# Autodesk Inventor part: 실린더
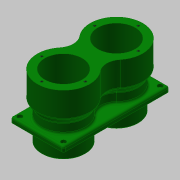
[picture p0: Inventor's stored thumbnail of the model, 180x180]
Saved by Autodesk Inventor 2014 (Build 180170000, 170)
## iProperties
Created: 2016-11
Part Number: 실린더
Material: 알루미늄 6061
Document SubType Name: Modeling
Designer: mduedu
Density: 2.71 g/cm^3
Mass: 1199.26 g
Surface Area: 1038.68 cm^2
Volume: 442.531 cm^3
Appearance: 진녹색
Author: mduedu
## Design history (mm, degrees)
sketch "스케치1"
  geometry: L1 (0, 0)-(0, 101); L2 (30, 0)-(30, 101); L3 (30, 101)-(42, 101); L4 (42, 101)-(42, 61); L5 (42, 61)-(35, 51); L6 (35, 51)-(35, 0); L7 (35, 0)-(30, 0)
  constraints: 14 end point, 4 parallel, 2 horizontal alignment, 1 perpendicular, 1 vertical
  dimensions: "d0" = 101 distance of L1.start L1.end; "d1" = 60 diameter of L2.end L1; "d2" = 84 diameter of L3.end L1; "d3" = 70 diameter of L6.end L1; "d4" = 40 distance of L3.end L4.end; "d5" = 50 vertical distance of L5.end L3.end
revolve "회전1" stored, may be unused: angle "d6" = 90 deg
node "작업 평면1"
sketch "스케치2"
  geometry: L1 (-42.5, -42.5)-(42.5, -42.5); L2 (42.5, -42.5)-(42.5, 42.5); L3 (42.5, 42.5)-(-42.5, 42.5); L4 (-42.5, 42.5)-(-42.5, -42.5); L5 (-42.5, -42.5)-(42.5, 42.5); L6 (42.5, -42.5)-(-42.5, 42.5); C1 r 35 at (0, 0) reference; C2 r 35 at (0, 0); 1 further point
  constraints: 12 end point, 2 midpoint, 2 parallel, 2 perpendicular, 1 centre point, 1 coincident, 1 concentric, 1 horizontal
  dimensions: "d8" = 85 distance of L2.end L3.end
extrude "돌출1" join sketch "스케치2" distance "d10" = 8; taper "d11" = 0 deg
chamfer "모따기1" distance "d14" = 1; stored, may be unused: second distance "d15" = 2, angle "d16" = 45 deg
chamfer "모따기2" distance "d17" = 5; stored, may be unused: second distance "d18" = 2, angle "d19" = 15 deg
sketch "스케치3"
  geometry: L1 (-35, -35)-(35, -35); L2 (35, -35)-(35, 35); L3 (35, 35)-(-35, 35); L4 (-35, 35)-(-35, -35); L5 (-35, -35)-(35, 35); L6 (35, -35)-(-35, 35); 3 further points
  constraints: 12 end point, 2 coincident, 2 midpoint, 2 parallel, 1 horizontal, 1 perpendicular
  dimensions: "d20" = 70 distance of L3.end L2.end; "d21" = 70 distance of L2.end L1.end
sketch "스케치4"
  geometry: 2 further points
  constraints: 2 other
hole "구멍1" sketch "스케치4" at (-35, 35), (35, 35) diameter "d22" = 4.5; stored, may be unused: countersink angle "d26" = 90 deg, drill point angle "d28" = 0 deg; dims "d23" = 6, "d24" = 8, "d25" = 4.6, "d27" = 8
sketch "스케치5"
  geometry: 3 further points
  constraints: 3 other
hole "구멍2" sketch "스케치5" at (35, 0), (-35, 0), (0, 35) diameter "d29" = 4.134; stored, may be unused: countersink angle "d33" = 90 deg, drill point angle "d35" = 120 deg; dims "d30" = 7.5, "d31" = 4, "d32" = 2, "d34" = 10
fillet "모깎기3" dims "d36" = 3
fillet "모깎기4" dims "d37" = 3
sketch "스케치6"
  geometry: L1 (0, 0)-(0, -85); A1 r 42 centre (0, 0) between (32.469, -26.642) and (-32.469, -26.642) reference; A2 r 42 centre (0, -85) between (32.469, -58.358) and (-32.469, -58.358) reference; A3 r 25 centre (51.795, -42.5) between (32.469, -58.358) and (32.469, -26.642); A4 r 25 centre (-51.795, -42.5) between (-32.469, -26.642) and (-32.469, -58.358); A5 r 25 centre (51.795, -42.5) between (32.469, -26.642) and (32.469, -58.358); A6 r 25 centre (-51.795, -42.5) between (-32.469, -58.358) and (-32.469, -26.642); A7 r 42 centre (0, 0) between (-32.469, -26.642) and (32.469, -26.642); A8 r 42 centre (0, -85) between (32.469, -58.358) and (-32.469, -58.358); A9 r 42 centre (0, 0) between (32.469, -26.642) and (-32.469, -26.642); A10 r 42 centre (0, -85) between (-32.469, -58.358) and (32.469, -58.358); 1 further point
  constraints: 20 point on circle, 8 centre point, 2 coincident, 2 end point, 2 tangent, 1 symmetric about line, 1 vertical, 1 other
  dimensions: "d38" = 50 diameter of A3
node "작업 평면2"
sketch "스케치7"
  geometry: A1 r 25 centre (9.795, -42.5) between (-9.531, -26.642) and (-9.531, -58.358) reference; A2 r 42 centre (-42, 0) between (-74.469, -26.642) and (-9.531, -26.642) reference; A3 r 42 centre (-42, -85) between (-9.531, -58.358) and (-74.469, -58.358) reference; A4 r 25 centre (-93.795, -42.5) between (-74.469, -58.358) and (-74.469, -26.642) reference; 1 further point
node "작업 평면3"
sketch "스케치8"
  geometry: L1 (-35, 0)-(-35, -85); A1 r 35 centre (-35, 0) between (-10.294, -24.792) and (-59.706, -24.792) reference; A2 r 35 centre (-35, -85) between (-10.294, -60.208) and (-59.706, -60.208) reference; A3 r 25 centre (7.353, -42.5) between (-10.294, -60.208) and (-10.294, -24.792); A4 r 25 centre (-77.353, -42.5) between (-59.706, -24.792) and (-59.706, -60.208); A5 r 25 centre (7.353, -42.5) between (-10.294, -24.792) and (-10.294, -60.208); A6 r 25 centre (-77.353, -42.5) between (-59.706, -60.208) and (-59.706, -24.792); A7 r 35 centre (-35, 0) between (-59.706, -24.792) and (-10.294, -24.792); A8 r 35 centre (-35, -85) between (-10.294, -60.208) and (-59.706, -60.208); 1 further point
  constraints: 16 point on circle, 6 centre point, 2 coincident, 2 end point, 2 tangent, 1 symmetric about line, 1 vertical, 1 other
  dimensions: "d40" = 50 diameter of A3
sketch "스케치9"
  geometry: A1 r 25 centre (42.353, -42.5) between (24.706, -24.792) and (24.706, -60.208) reference; A2 r 35 centre (0, 0) between (-24.706, -24.792) and (24.706, -24.792) reference; A3 r 35 centre (0, -85) between (24.706, -60.208) and (-24.706, -60.208) reference; A4 r 25 centre (-42.353, -42.5) between (-24.706, -60.208) and (-24.706, -24.792) reference; 1 further point
feature "로프트1" sketch "스케치8", "스케치9" dims "d42" = 0, "d43" = 90 deg, "d44" = 0, "d45" = 90 deg
feature "로프트2" dims "d46" = 0, "d47" = 90 deg, "d48" = 0, "d49" = 90 deg
  node "모서리1"
feature "로프트3" dims "d50" = 0, "d51" = 90 deg, "d52" = 0, "d53" = 90 deg
  node "모서리2"
fillet "모깎기5" dims "d54" = 3
node "솔리드1"
mirror "대칭1"
other parameters: "d7" = -27
